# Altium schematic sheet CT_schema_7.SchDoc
size 371 x 245 mm
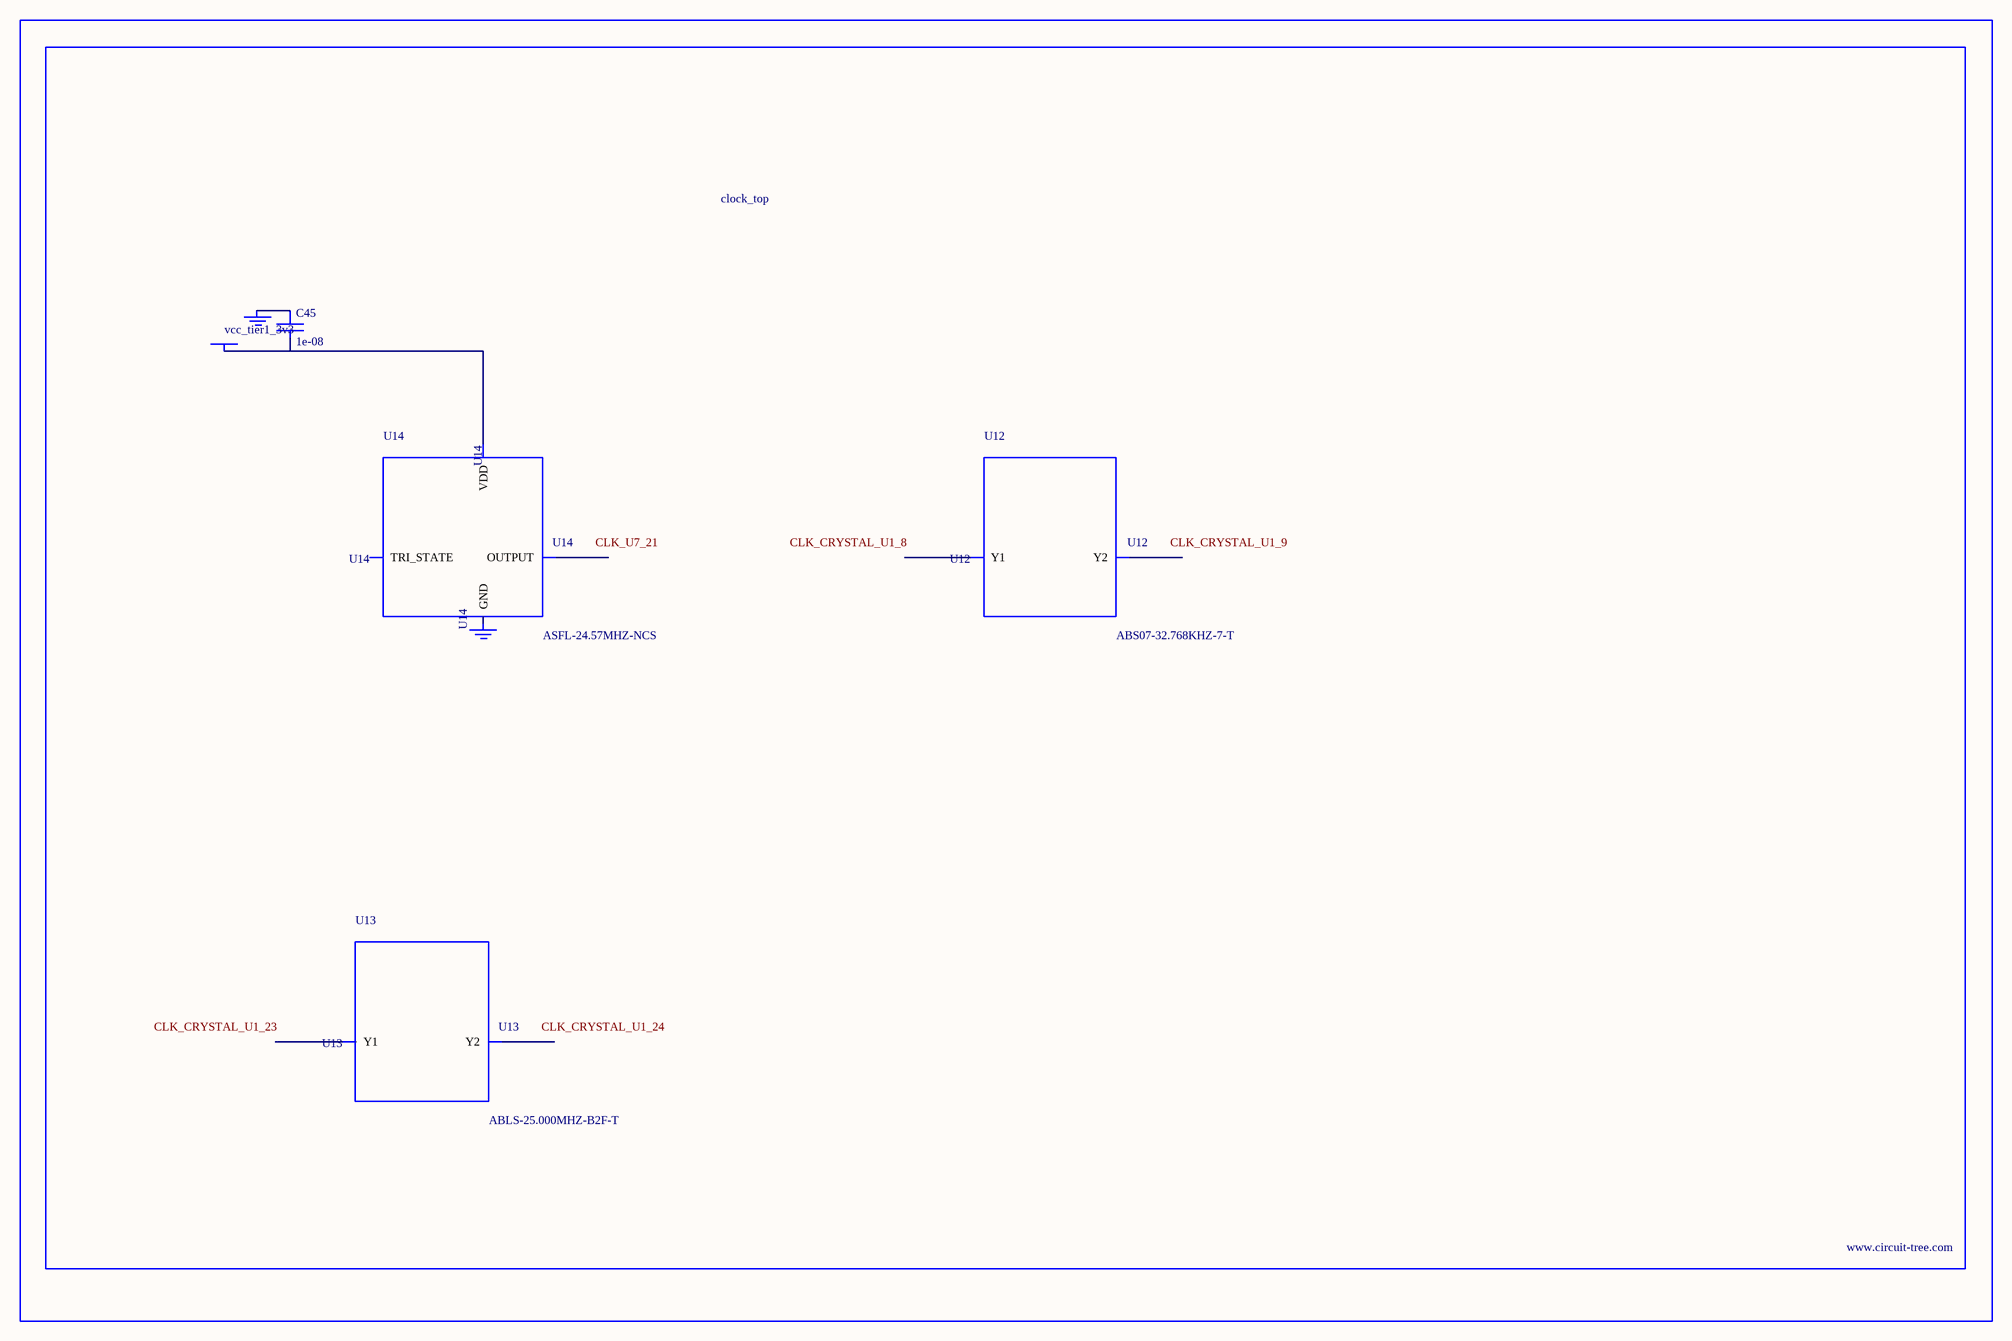
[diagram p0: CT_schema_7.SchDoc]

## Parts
BORDER6  (no value)
C45  1e-08  [C0402]
GND_INSTANCE_6_0  (no value)
GND_INSTANCE_6_1  (no value)
POWER_INSTANCE_6_0  vcc_tier1_3v3
U12  ABS07-32.768KHZ-7-T  [ABS07-32.768KHZ-7-T]
U13  ABLS-25.000MHZ-B2F-T  [ABLS-25.000MHZ-B2F-T]
U14  ASFL-24.57MHZ-NCS  [ASFL1]

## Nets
NetC45_1: C45.1 GND_INSTANCE_6_0.0(GND)
NetC45_2: C45.2 POWER_INSTANCE_6_0.0(PWR) U14.4(VDD)

Not connected (* = marked no-connect by the designer): GND_INSTANCE_6_1 0(GND); U12 1(Y1) 2(Y2); U13 1(Y1) 2(Y2); U14 1(TRI_STATE) 2(GND) 3(OUTPUT)

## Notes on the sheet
- Labels drawn without touching a wire or pin: CLK_CRYSTAL_U1_8, CLK_CRYSTAL_U1_9, CLK_CRYSTAL_U1_23, CLK_CRYSTAL_U1_24, CLK_U7_21

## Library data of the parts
BORDER6 = BORDER_PAGE6
C45 = C0402C103K3RAC
GND_INSTANCE_6_0 GND_INSTANCE_6_1 = GND
POWER_INSTANCE_6_0 = PWR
